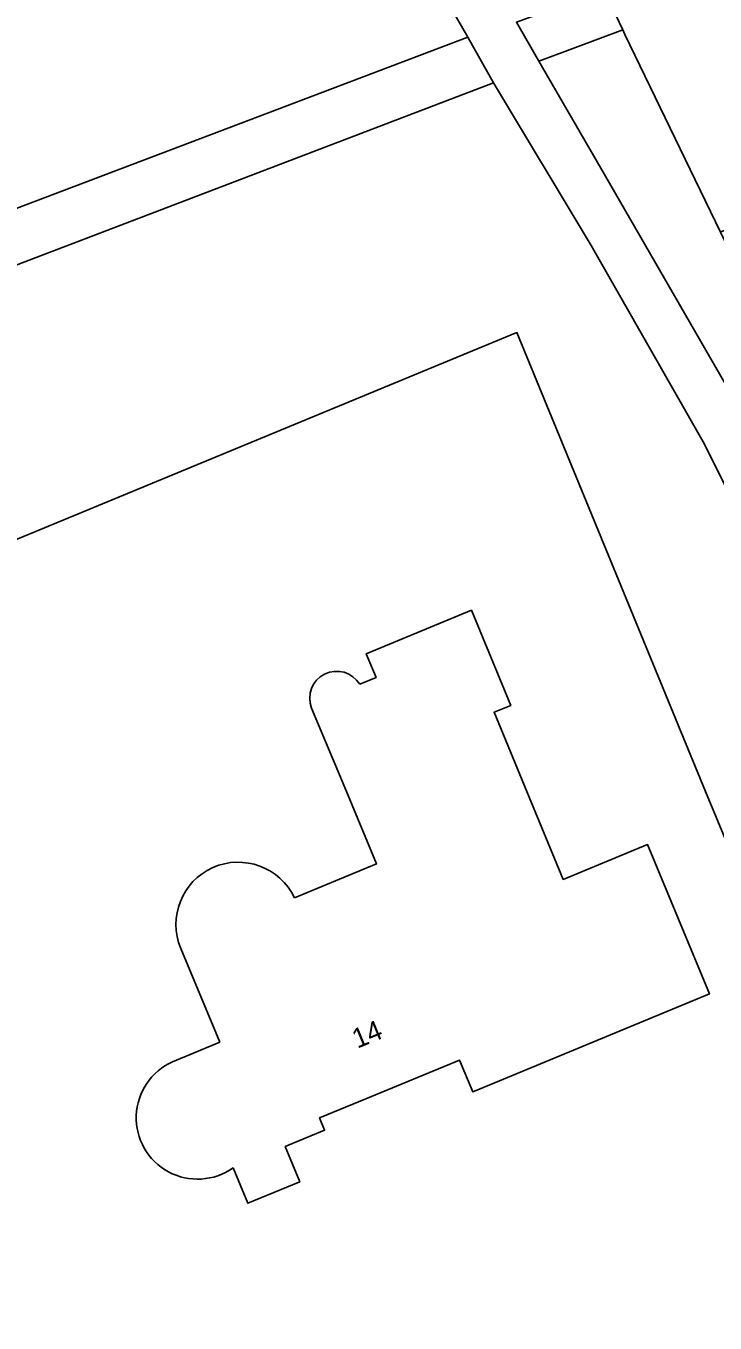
# Model space of a CAD drawing. Extents: x 162417 to 163722, y 384268 to 385417.
# Drawn here: x 163284 to 163319, y 384972.9 to 385039 of the extents above; entities that cross this region are included whole.
import ezdxf

# ---------------------------------------------------------------- set-up
doc = ezdxf.new("R2010")
doc.units = 0
for name, color, linetype in [('IMGEO_Berm_groen', 7, 'Continuous'), ('IMGEO_Erf', 7, 'Continuous'), ('IMGEO_Gemengd_bos', 7, 'Continuous'), ('IMGEO_Groenvoorziening', 7, 'Continuous'), ('IMGEO_Pand', 7, 'Continuous'), ('IMGEO_Pand_nummerreeks', 7, 'Continuous'), ('IMGEO_Rijbaan_lokaal_gesloten', 7, 'Continuous'), ('IMGEO_Voetpad_halfverhard', 7, 'Continuous'), ('IMGEO_Voetpad_open', 7, 'Continuous')]:
    doc.layers.add(name, color=color, linetype=linetype)

msp = doc.modelspace()

# ---------------------------------------------------------------- linework, layer by layer
at = {"layer": 'IMGEO_Berm_groen'}
msp.add_lwpolyline([(163326.303, 385014.043), (163321.435, 385024.117), (163321.045, 385024.924), (163319.33, 385028.472), (163314.463, 385038.546), (163314.352, 385038.78), (163310.406, 385037.308), (163310.086, 385037.189), (163313.243, 385031.731), (163321.305, 385017.726), (163324.433, 385011.035), (163327.026, 385005.491), (163329.506, 384999.362), (163331.877, 384992.906), (163334.793, 384983.636), (163336.199, 384978.01), (163336.54, 384978.154), (163337.564, 384978.789)], dxfattribs=at)
at = {"layer": 'IMGEO_Erf'}
msp.add_lwpolyline([(163318.553, 385000), (163308.966, 385023.36), (163277.359, 385010.294), (163269.662, 385007.068), (163253.071, 385000), (163231.527, 384990.762), (163201.717, 384977.798), (163182.103, 384971.2), (163157.341, 384961.784), (163158.508, 384959.069), (163175.467, 384919.624), (163175.758, 384919.851), (163183.667, 384913.961), (163328.962, 384974.963)], close=True, dxfattribs=at)
for points in [[(163300.965, 385005.456), (163301.797, 385005.801), (163301.299, 385007.006), (163306.649, 385009.218), (163308.65, 385004.379), (163307.805, 385004.029), (163309.472, 385000), (163311.324, 384995.519), (163315.613, 384997.293), (163318.761, 384989.681), (163307.088, 384984.854), (163306.714, 384984.699), (163306.046, 384986.314), (163301.276, 384984.342), (163298.92, 384983.368), (163299.179, 384982.742), (163297.177, 384981.915), (163297.918, 384980.123), (163295.267, 384979.026), (163294.523, 384980.826)], [(163297.647, 384994.577), (163301.819, 384996.302), (163300.29, 385000), (163298.517, 385004.24)], [(163291.445, 384986.227), (163293.846, 384987.235), (163291.863, 384992.002)]]:
    msp.add_lwpolyline(points, dxfattribs=at)
for centre, radius, start, end in [((163299.793, 385004.743), 1.372, 31.33987, 201.49025), ((163294.783, 384993.226), 3.166, 25.2476, 202.74905), ((163292.72, 384983.376), 3.123, 114.10288, 305.25427)]:
    msp.add_arc(centre, radius, start, end, dxfattribs=at)
at = {"layer": 'IMGEO_Gemengd_bos'}
msp.add_lwpolyline([(163326.615, 385000.058), (163321.211, 385012.274), (163318.448, 385017.802), (163312.737, 385027.803), (163307.775, 385036.08), (163264.453, 385019.528), (163277.359, 385010.294), (163308.966, 385023.36), (163318.553, 385000), (163328.962, 384974.963), (163333.911, 384977.041), (163329.908, 384990.952)], close=True, dxfattribs=at)
at = {"layer": 'IMGEO_Groenvoorziening'}
msp.add_lwpolyline([(163286.021, 385076.358), (163104.307, 385022.265), (163122.658, 385000), (163138.541, 384980.681), (163155.601, 384987.18), (163164.637, 384990.34), (163190.458, 384998.345), (163192.604, 385009.043), (163194.693, 385015.882), (163196.064, 385017.566), (163203.308, 385025.478), (163206.676, 385027.672), (163212.001, 385029.943), (163221.097, 385031.577), (163228.409, 385031.373), (163249.98, 385025.798), (163256.091, 385024.664), (163270.812, 385024.868), (163306.472, 385038.41), (163291.632, 385064.162)], dxfattribs=at)
at = {"layer": 'IMGEO_Pand'}
for points in [[(163294.523, 384980.826), (163295.267, 384979.026), (163297.918, 384980.123), (163297.177, 384981.915), (163299.179, 384982.742), (163298.92, 384983.368), (163301.276, 384984.342), (163306.046, 384986.314), (163306.714, 384984.699), (163307.088, 384984.854), (163318.761, 384989.681), (163315.613, 384997.293), (163311.324, 384995.519), (163309.472, 385000), (163307.805, 385004.029), (163308.65, 385004.379), (163306.649, 385009.218), (163301.299, 385007.006), (163301.797, 385005.801), (163300.965, 385005.456)], [(163298.517, 385004.24), (163300.29, 385000), (163301.819, 384996.302), (163297.647, 384994.577)], [(163291.863, 384992.002), (163293.846, 384987.235), (163291.445, 384986.227)]]:
    msp.add_lwpolyline(points, dxfattribs=at)
for centre, radius, start, end in [((163299.793, 385004.743), 1.372, 31.33987, 201.49025), ((163294.783, 384993.226), 3.166, 25.2476, 202.74905), ((163292.72, 384983.376), 3.123, 114.10288, 305.25427)]:
    msp.add_arc(centre, radius, start, end, dxfattribs=at)
at = {"layer": 'IMGEO_Rijbaan_lokaal_gesloten'}
msp.add_lwpolyline([(163290.255, 385089.172), (163293.289, 385082.487), (163294.869, 385079.247), (163297.429, 385073.995), (163302.667, 385063.063), (163309.195, 385049.593), (163313.384, 385040.81), (163314.352, 385038.78), (163314.463, 385038.546), (163319.33, 385028.472), (163325.621, 385031.431), (163324.885, 385032.981), (163322.267, 385038.087), (163321.067, 385040.629), (163319.914, 385043.073), (163315.984, 385051.399), (163310.522, 385062.735), (163305.2, 385074.098), (163300.642, 385083.502), (163287.885, 385109.82)], dxfattribs=at)
at = {"layer": 'IMGEO_Voetpad_halfverhard'}
for points in [[(163313.384, 385040.81), (163309.318, 385039.309), (163308.94, 385039.17), (163310.086, 385037.189), (163310.406, 385037.308), (163314.352, 385038.78)], [(163191.128, 384995.57), (163206.966, 385000), (163221.419, 385003.913), (163225.935, 385005.281), (163236.315, 385008.778), (163264.453, 385019.528), (163307.775, 385036.08), (163306.472, 385038.41), (163270.812, 385024.868), (163231.847, 385010.07), (163220.466, 385006.34), (163207.262, 385002.939), (163196.665, 385000), (163190.458, 384998.345), (163164.637, 384990.34), (163155.601, 384987.18), (163138.541, 384980.681), (163140.375, 384978.496), (163154.336, 384983.85), (163165.108, 384987.676), (163170.476, 384989.305)]]:
    msp.add_lwpolyline(points, close=True, dxfattribs=at)
at = {"layer": 'IMGEO_Voetpad_open'}
msp.add_lwpolyline([(163291.632, 385064.162), (163306.472, 385038.41), (163307.775, 385036.08), (163312.737, 385027.803), (163318.448, 385017.802), (163321.211, 385012.274), (163326.615, 385000.058), (163329.908, 384990.952), (163333.911, 384977.041), (163336.199, 384978.01), (163334.793, 384983.636), (163331.877, 384992.906), (163329.506, 384999.362), (163327.026, 385005.491), (163324.433, 385011.035), (163321.305, 385017.726), (163313.243, 385031.731), (163310.086, 385037.189), (163308.94, 385039.17)], dxfattribs=at)

# ---------------------------------------------------------------- texts
at = {"layer": 'IMGEO_Pand_nummerreeks'}
msp.add_text('14', height=1, rotation=22.46097, dxfattribs=at).set_placement((163300.841, 384986.889))

doc.saveas('drawing.dxf')
